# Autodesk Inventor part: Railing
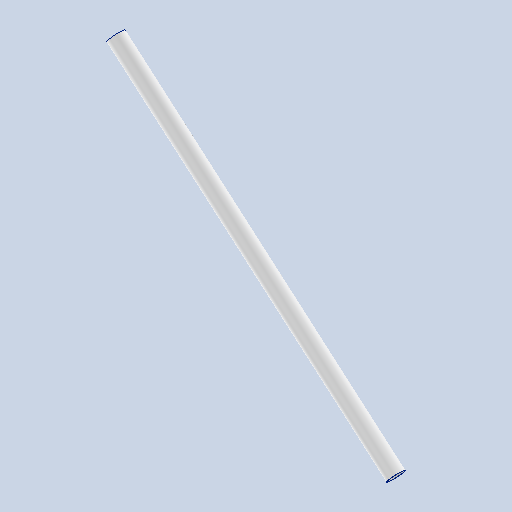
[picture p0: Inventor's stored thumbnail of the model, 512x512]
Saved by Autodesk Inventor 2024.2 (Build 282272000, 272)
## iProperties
Created: 2022-06
Part Number: Railing
Material: Aluminum 6061
Document SubType Name: Modeling
Designer: reaumed
Density: 2.7 g/cm^3
Appearance: Aluminum - Flat
Mass: 1627.16 g
Surface Area: 4753.01 cm^2
Volume: 602.654 cm^3
Author: reaumed
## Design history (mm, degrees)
workplane "Work Plane1"
workplane "Work Plane3"
  workplane "Work Plane2"
workplane "Work Plane4"
revolve "Revolution1" stored, may be unused: angle "d19" = 360 deg
shell "Shell1" dims "d20" = 2.54
body "Solid2"
sketch "Sketch1"
  geometry: L1 (0, 819.15)-(-914.4, 57.15); L2 (-1126.921, 723.9)-(246.904, 723.9) reference; L3 (-1126.921, -190.5)-(246.904, -190.5) reference; L4 (-16.261, 838.663)-(-930.661, 76.663); L5 (-114.3, -250.623)-(-114.3, 1071.007) reference; L6 (0, -250.623)-(0, 1071.007) reference; L7 (0, 819.15)-(-16.261, 838.663); L8 (-914.4, 57.15)-(-930.661, 76.663); L9 (50.643, 758.378)-(-922.53, 66.906); 5 further points
  constraints: 10 end point, 6 point on line, 2 perpendicular, 1 midpoint, 1 parallel
  dimensions: "d4" = 39.8056 deg angle of L1 L3 (= RailingAngle); "d12" = 25.4 distance between parallel lines of L1 L4 (= 0.5 x RailingThickness); "d13" = 0 distance from line of L2 point (-114.3, 723.9); "d14" = 914.4 distance from line of point (-914.4, -61.819) L6 (= RailingRun); "d16" = 1190.28205 distance of L1.start L1.end (= RailingStockLength)
other parameters: "Width" = 762 [user parameter; used in 1 equation term], "Rise" = 190.5 [user parameter; used in 1 equation term], "Run" = 228.6 [user parameter; used in 1 equation term], "RailingWidth" = 76.2 [user parameter], "RailingThickness" = 50.8 [user parameter; used in 2 equation terms], "RailingStockLength" = 1190.28205 [user parameter; used in 1 equation term], "RailingAngle" = 39.8056 deg [user parameter; used in 1 equation term], "d0" = 361.95 (= 0.5 x Width - 0.5 x StringerThickness), "BalusterLength" = 914.4 [user parameter; used in 1 equation term], "d1" = -190.5 (= -Rise), "d2" = 914.4 (= BalusterLength), "d6" = 50.8 (= RailingThickness), "d11" = 114.3 (= 0.5 x Run), "RailingRun" = 914.4 [user parameter; used in 1 equation term], "d15" = 1808.46777 (derived), "StringerThickness" = 38.1 [user parameter; used in 1 equation term]
